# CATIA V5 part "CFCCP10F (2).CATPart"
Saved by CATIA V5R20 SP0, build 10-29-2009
Part number: CFCCP10F (2)
Revision: TUTTO
Definition: NON CONOSCIUTO
Nomenclature: CFCCP10F (2)
Source: Unknown
Bounding box of the stored display mesh (mm): x -50 to 50, y -29 to 29, z -55 to 0
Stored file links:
  C:\Users\Utente\Desktop\IO LAVORO\3D X SITO CF\X 3D SITO CF 27-09-2020\CFCCP\CFCCP10F\CFCCP10F (2).CATPart
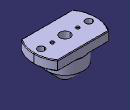
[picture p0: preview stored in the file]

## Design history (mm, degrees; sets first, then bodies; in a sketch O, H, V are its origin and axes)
Body1 "Foro filettato M5-1" (main body)
  Solid1: solid without history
